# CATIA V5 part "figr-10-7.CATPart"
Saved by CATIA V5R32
Part number: Part1
Bounding box of the stored display mesh (mm): x -9.616 to 10, y -9.533 to 9.835, z 0 to 10
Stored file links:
  D:\PROJECTS\Project 2022\CATIA V5 6R 2022\Resources\Part Files\c10_catia_v5_6r2022_prt\c10_catia_v5_6r2022_prt\figr-10-7.CATPart
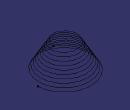
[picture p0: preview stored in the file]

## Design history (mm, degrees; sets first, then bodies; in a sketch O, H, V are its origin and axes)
Set1
  Helix1: Direction {line stored without definition}, RefPoint {point type Coord, X 10, Y 0, Z 0}, Pitch 1, Height 10, TaperAngle 30
Body1 (main body)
